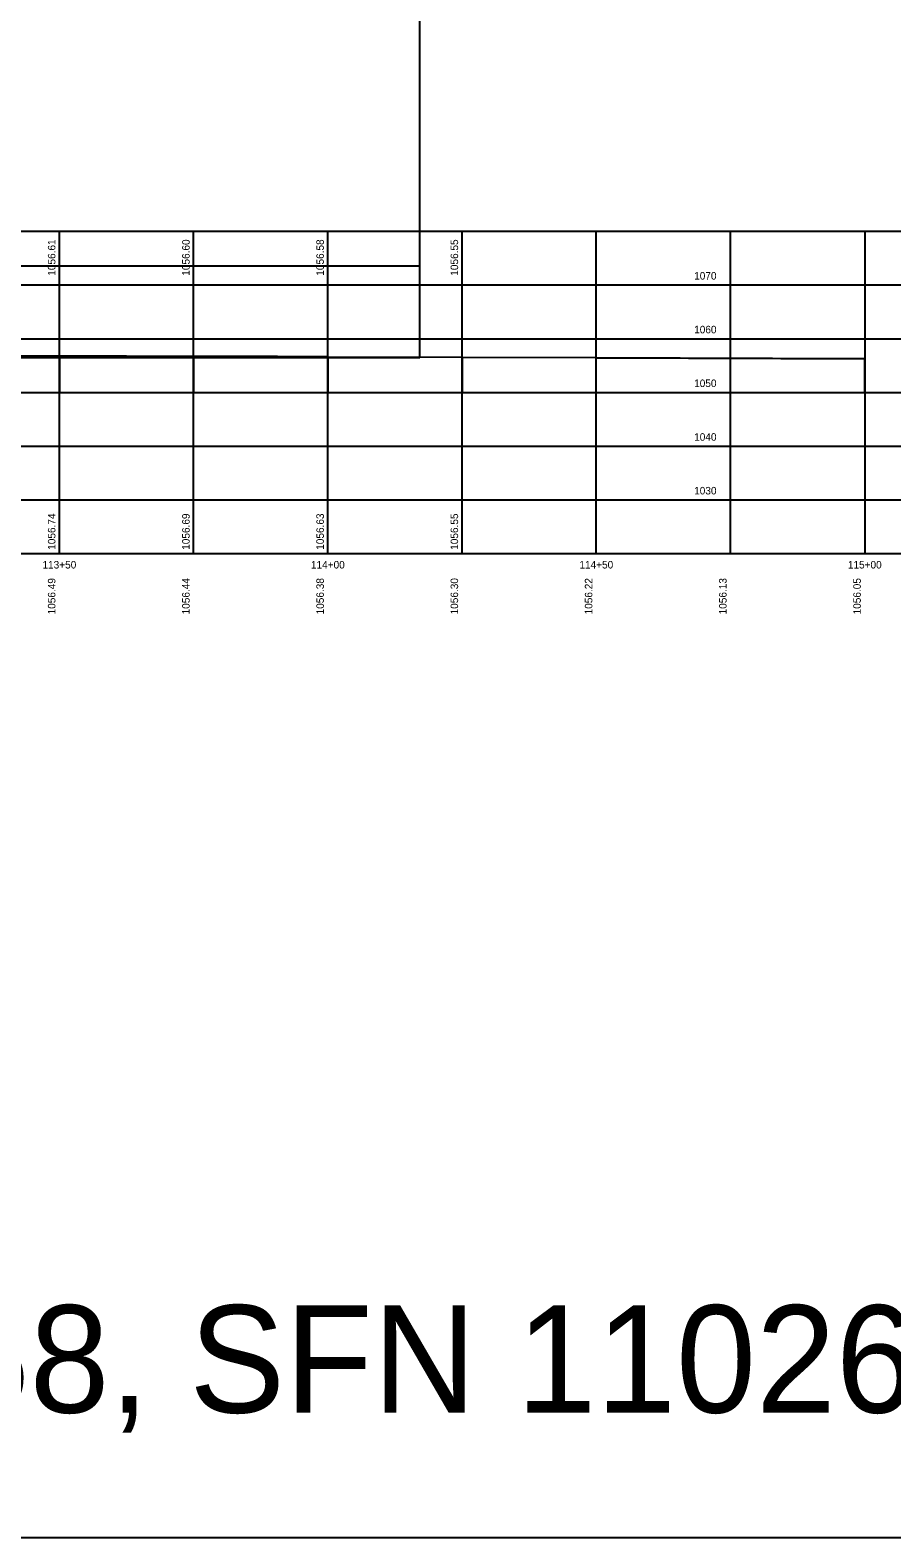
# Model space of a CAD drawing. Extents: x -2063 to 2068, y 79 to 1202.
# Drawn here: x -1524.8 to -1364.3, y 78.7 to 359.4 of the extents above; entities that cross this region are included whole.
import ezdxf

# ---------------------------------------------------------------- set-up
doc = ezdxf.new("R2010")
doc.units = 0
for name, color, linetype in [('PF_X_Ground_Line', 7, 'Continuous'), ('SC_Scratch1', 7, 'Continuous'), ('SC_Scratch2', 7, 'Continuous'), ('SC_Scratch3', 7, 'Continuous'), ('XS_P_Pavt_Surface', 7, 'Continuous')]:
    doc.layers.add(name, color=color, linetype=linetype)

msp = doc.modelspace()

# ---------------------------------------------------------------- linework, layer by layer
at = {"layer": 'PF_X_Ground_Line'}
msp.add_line((-1469.33, 298.6), (-1419.33, 298.44), dxfattribs=at)
for centre, radius, start, end in [((-1631.83, -62201.38), 62500.19, 89.8968677, 89.9270098), ((-1631.83, -62201.65), 62500.46, 89.8510313, 89.8968677), ((-1181.82, 62799.07), 62501.09, 269.7822771, 269.8281131)]:
    msp.add_arc(centre, radius, start, end, dxfattribs=at)
at = {"layer": 'SC_Scratch1'}
for p, q in [((-1969.33, 321.97), (-1244.33, 321.97)), ((-1519.33, 261.97), (-1519.33, 321.97)), ((-1494.33, 261.97), (-1494.33, 321.97)), ((-1469.33, 261.97), (-1469.33, 321.97)), ((-1444.33, 261.97), (-1444.33, 321.97)), ((-1419.33, 261.97), (-1419.33, 321.97)), ((-1394.33, 261.97), (-1394.33, 321.97)), ((-1369.33, 321.97), (-1369.33, 261.97)), ((-1969.33, 311.97), (-1244.33, 311.97)), ((-1969.33, 301.97), (-1244.33, 301.97)), ((-1969.33, 291.97), (-1244.33, 291.97)), ((-1969.33, 281.97), (-1244.33, 281.97)), ((-1969.33, 271.97), (-1244.33, 271.97)), ((-1969.33, 261.97), (-1244.33, 261.97))]:
    msp.add_line(p, q, dxfattribs=at)
msp.add_lwpolyline([(-2062.8, 512.75), (-1164.75, 512.75), (-1164.75, 78.7), (-2062.8, 78.7)], close=True, dxfattribs=at)
at = {"layer": 'SC_Scratch2'}
for p, q in [((-1519.33, 298.57), (-1519.33, 291.97)), ((-1494.33, 298.56), (-1494.33, 291.97)), ((-1469.33, 298.55), (-1469.33, 291.97)), ((-1444.33, 298.52), (-1444.33, 291.97))]:
    msp.add_line(p, q, dxfattribs=at)
at = {"layer": 'SC_Scratch3'}
for p, q in [((-1452.21, 298.54), (-1452.21, 1078.77)), ((-1552.21, 315.53), (-1452.21, 315.53)), ((-1519.33, 298.71), (-1519.33, 291.97)), ((-1494.33, 291.97), (-1494.33, 298.66)), ((-1469.33, 291.97), (-1469.33, 298.6)), ((-1444.33, 291.97), (-1444.33, 298.52)), ((-1419.33, 291.97), (-1419.33, 298.44)), ((-1394.33, 291.97), (-1394.33, 298.35)), ((-1369.33, 291.97), (-1369.33, 298.27))]:
    msp.add_line(p, q, dxfattribs=at)
at = {"layer": 'XS_P_Pavt_Surface'}
for p, q in [((-1552.21, 298.59), (-1452.21, 298.54)), ((-1452.21, 298.4), (-1527.21, 298.43)), ((-1452.21, 298.54), (-1452.21, 298.4))]:
    msp.add_line(p, q, dxfattribs=at)

# ---------------------------------------------------------------- texts
at = {"layer": 'SC_Scratch1'}
for s, p in [('1056.61', (-1520.06, 313.69)), ('1056.60', (-1495.06, 313.69)), ('1056.58', (-1470.06, 313.69)), ('1056.55', (-1445.06, 313.69)), ('1056.74', (-1520.06, 262.66)), ('1056.69', (-1495.06, 262.66)), ('1056.63', (-1470.06, 262.66)), ('1056.55', (-1445.06, 262.66)), ('1056.49', (-1520.06, 250.63)), ('1056.44', (-1495.06, 250.63)), ('1056.38', (-1470.06, 250.63)), ('1056.30', (-1445.06, 250.63)), ('1056.22', (-1420.06, 250.63)), ('1056.13', (-1395.06, 250.63)), ('1056.05', (-1370.06, 250.63))]:
    msp.add_text(s, height=1.4, rotation=90, dxfattribs=at).set_placement(p)
for s, height, p in [('1070', 1.4, (-1401.1, 312.97)), ('1060', 1.4, (-1401.1, 302.97)), ('1050', 1.4, (-1401.1, 292.97)), ('1040', 1.4, (-1401.1, 282.97)), ('1030', 1.4, (-1401.1, 272.97)), ('113+50', 1.4, (-1522.47, 259.18)), ('114+00', 1.4, (-1472.47, 259.18)), ('114+50', 1.4, (-1422.47, 259.18)), ('115+00', 1.4, (-1372.47, 259.18)), ('REF: PID 114958, SFN 1102672 PROFILE', 20, (-1719.6, 102.01))]:
    msp.add_text(s, height=height, dxfattribs=at).set_placement(p)

doc.saveas('drawing.dxf')
